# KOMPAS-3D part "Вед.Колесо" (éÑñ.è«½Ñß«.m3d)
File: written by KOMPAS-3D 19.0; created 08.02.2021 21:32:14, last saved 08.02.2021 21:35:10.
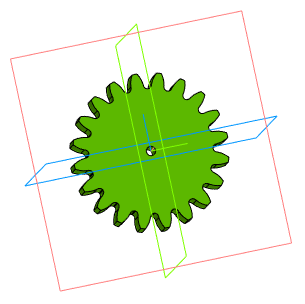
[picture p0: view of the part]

Document properties: Автор: Agent Smith; Полное имя файла: D:\3D_print\3D проекты Компас 3D\Халява Projects 5\Вед.Колесо.m3d

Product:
- Part/product: Вед.Колесо
    Материал: АБС 0603Т ТУ 2214-019-002 03521-96 (density 0 kg/m3)

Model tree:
1. ЛСК (Шестерня цилиндрическая с внешними зубьями):1  (with: Шестерня цилиндрическая с внешними зубьями:1, Плоскость XY, Плоскость ZX, Плоскость ZY, Ось X, Ось Y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)  (labels: &Фаска (Шестерня цилиндрическая с внешними зубьями):1)
     Ось X. X = 1; Ось Y. Y = 1; Ось Z. Z = 1; Угол 1 = 360
2. Эскиз для винтовой линии (Шестерня цилиндрическая с внешними зубьями):1  (with: Винтовая линия (Шестерня цилиндрическая с внешними зубьями):1, Шестерня цилиндрическая с внешними зубьями:1, Впадина прямая (Шестерня цилиндрическая с внешними зубьями):1, Впадина косая (Шестерня цилиндрическая с внешними зубьями):1, Массив впадин (Шестерня цилиндрическая с внешними зубьями):1)  (2 pattern instances)
     Число витков = 0.00742627; Смещение 2 = 8
3. Впадина прямая (Шестерня цилиндрическая с внешними зубьями):1  (with: Массив впадин (Шестерня цилиндрическая с внешними зубьями):1, Шестерня цилиндрическая с внешними зубьями:1)  (20 pattern instances)
     N 1 = 1; Шаг 1 = 1; Номер 1 = 1
4. Впадина косая (Шестерня цилиндрическая с внешними зубьями):1  (with: Винтовая линия (Шестерня цилиндрическая с внешними зубьями):1)
     N 1 = 1; Шаг 1 = 1; Номер 1 = 1
5. Шестерня цилиндрическая с внешними зубьями:1
6. Эскиз:5  (with: Цилиндр (Шестерня цилиндрическая с внешними зубьями):1, Впадина прямая (Шестерня цилиндрическая с внешними зубьями):1)
7. Элемент выдавливания:3  (labels: АБС 0603Т ТУ 2214-019-002 03521-96)

Expressions: (VGExtS_1_z*VGExtS_1_M)/COSD(VGExtS_1_Beta); 360/VGExtS_1_z
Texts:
  SHAFT3D
  Количество отображаемых зубьев
  Угол наклона линии зубьев
  Шаг по кольцевому направлению
  (VGExtS_1_Beta>0)?(M_PI*VGExtS_1_z*VGExtS_1_M/SIND(VGExtS_1_Beta)):1000
  (VGExtS_1_Da<=0||VGExtS_1_Da>5e+7)?25:VGExtS_1_Da
  (VGExtS_1_H<=0||VGExtS_1_H>5e+7)?25:VGExtS_1_H
  VGExtS_1_zz<VGExtS_1_z?(VGExtS_1_zz+1):VGExtS_1_z
  (VGExtS_1_zz<=0||VGExtS_1==1)||(VGExtS_1_Beta>0)?1:0
  (VGExtS_1_zz<=0||VGExtS_1==1)||(VGExtS_1_Beta<=0)?1:0
  (VGExtS_1==1)||(VGExtS_1_Beta<=0)?1:0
